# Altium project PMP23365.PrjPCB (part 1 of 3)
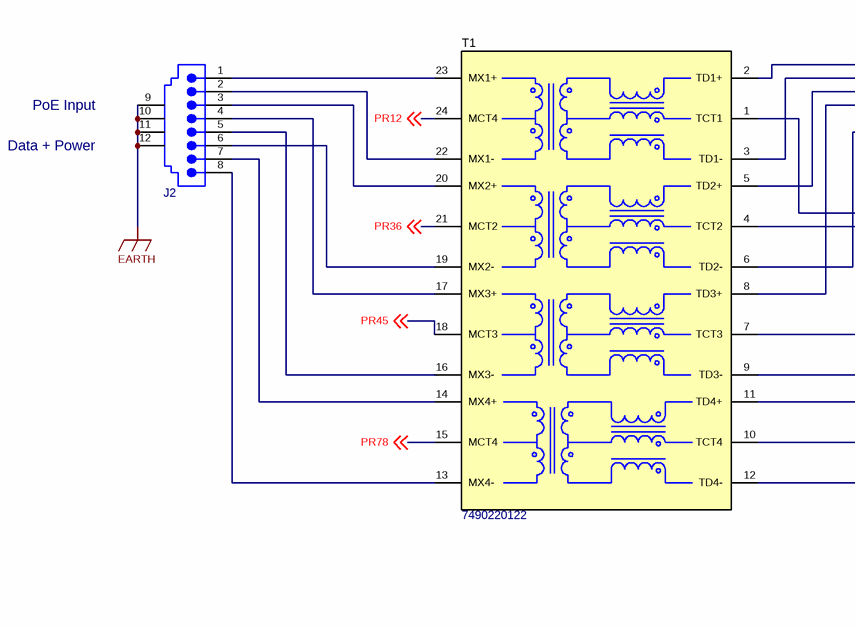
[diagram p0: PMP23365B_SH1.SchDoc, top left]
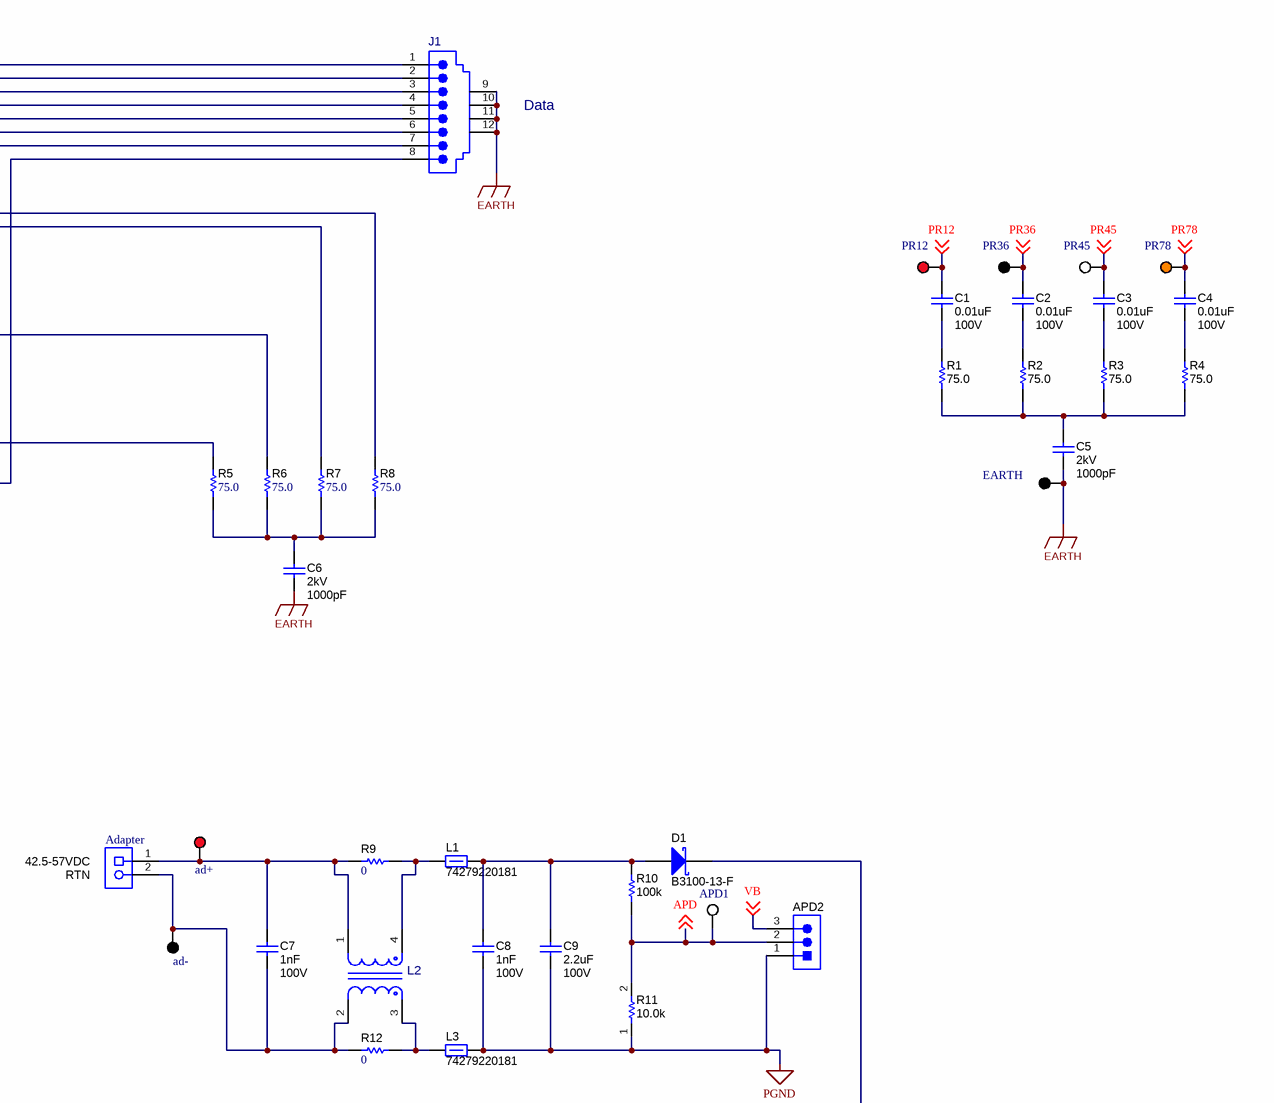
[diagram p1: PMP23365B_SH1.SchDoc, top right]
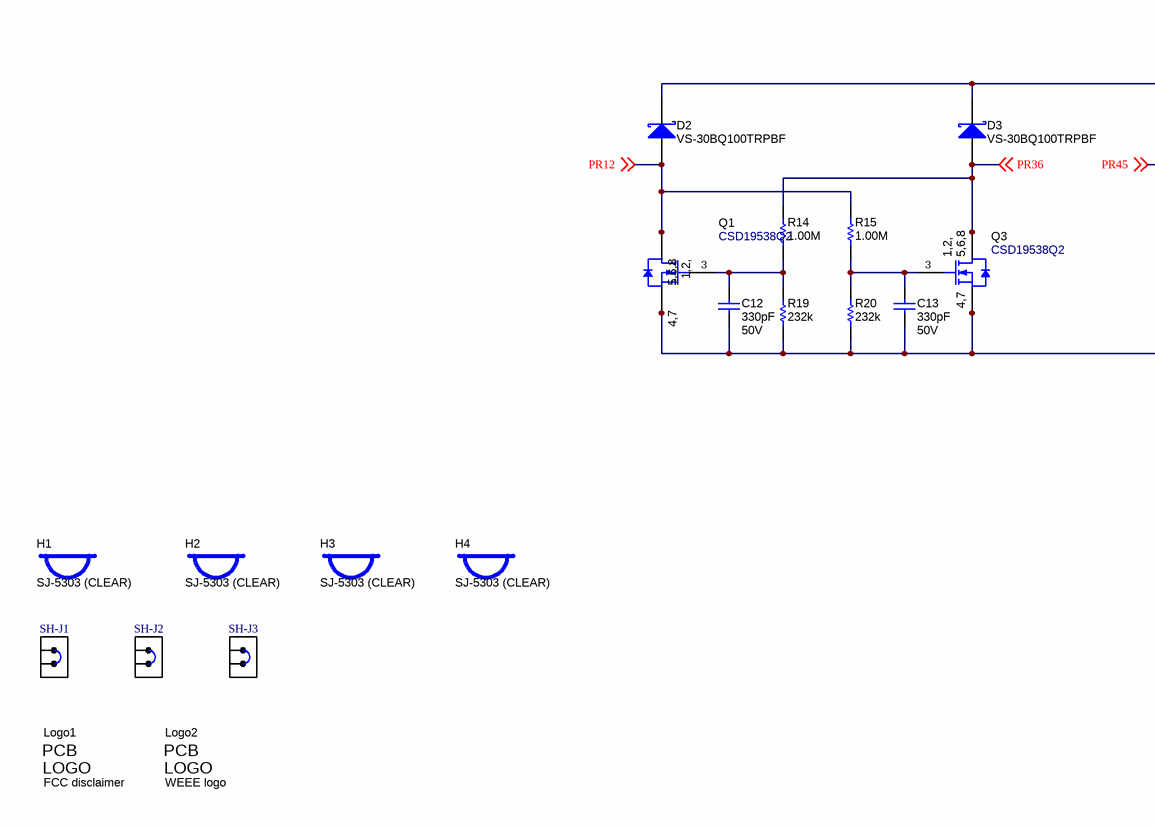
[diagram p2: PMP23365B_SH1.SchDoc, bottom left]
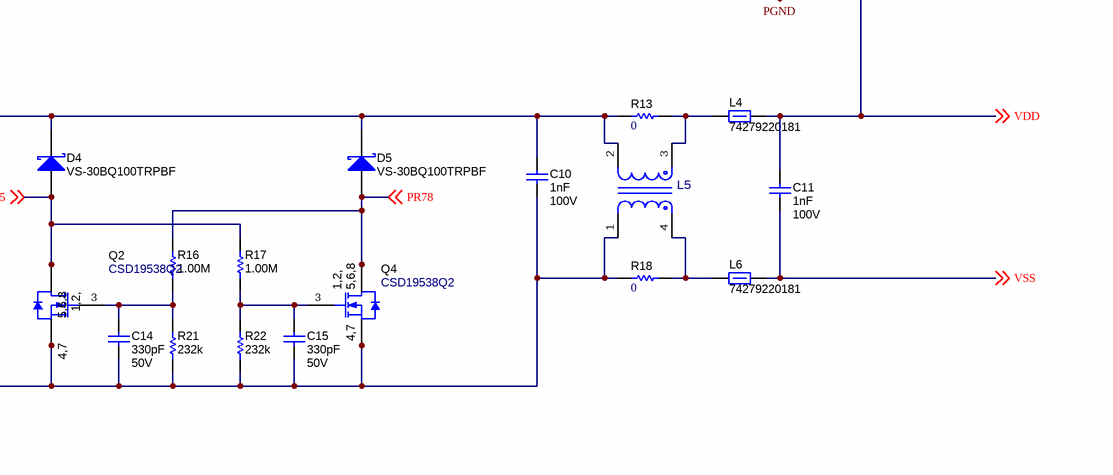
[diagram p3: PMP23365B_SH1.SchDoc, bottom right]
CopyrightYear: 2023; PCB_Layout: N/A; PCB_Rev: B; PRJ_Customer: Public Release; PRJ_Engineer: D Xing; PRJ_Number: PMP23365; PRJ_Title: TPS23730 with Telemetry at CLS8, 24V/3A; SCH_Rev: B; TechSupport: N/A; TID: N/A
3 sheets, 303 parts. Net scope: global (net labels, ports and power ports of the same name join across sheets).
Board file: PMP23365B.PcbDoc
Sheets:
  PMP23365B_SH1.SchDoc
  PMP23365B_SH2.SchDoc
  PMP23365B_SH3.SchDoc

## Sheet PMP23365B_SH1.SchDoc: PoE Input
size 558 x 431 mm; Date: Not shown in title block; ApprovedBy: Not shown in title block; CheckedBy: Not shown in title block; Author: Not shown in title block; CompanyName: Not shown in title block; DrawnBy: D Xing; Engineer: Not shown in title block; Organization: Not shown in title block; Address1: Not shown in title block; Address2: Not shown in title block; Address3: Not shown in title block; Address4: Not shown in title block; DocumentNumber: 1; Revision: Use project parameter SCH_Rev; SheetNumber: 1; SheetTotal: 3; PageSetup: Record=PageOptions¦CenterHorizontal=True¦CenterVertical=True¦PrintScale=1.00¦XCorrection=1.00¦YCorrection=1.00¦PrintKind=0¦BorderSize=5000000¦LeftOffset=0¦BottomOffset=0¦Orientation=2¦PaperLength=1000¦PaperWidth=1000¦Scale=100¦PaperSource=15¦PrintQuality=600¦MediaType=1¦DitherType=10¦PaperKind=Letter¦PrintScaleMode=1

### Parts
ad+  5000  [Keystone5000]  (value not drawn)
ad-  5001  [Keystone5001]  (value not drawn)
Adapter  CMP-0074913-1  [TERM_BLK_ED555-2DS]  (value not drawn)
APD1  5002  [Keystone5002]  (value not drawn)
APD2  5-146278-3  [TE_5-146278-3]  (value not drawn)
C1  ValueDisplayed: 0.01uF  Value2: 100V  [0603L]  (hidden comment: Capacitor)
C2  ValueDisplayed: 0.01uF  Value2: 100V  [0603L]  (hidden comment: Capacitor)
C3  ValueDisplayed: 0.01uF  Value2: 100V  [0603L]  (hidden comment: Capacitor)
C4  ValueDisplayed: 0.01uF  Value2: 100V  [0603L]  (hidden comment: Capacitor)
C5  VDC_V: 2kV  ValueDisplayed: 1000pF  [1812]  (hidden comment: GR443QR73D102KW01L)
C6  VDC_V: 2kV  ValueDisplayed: 1000pF  [1812]  (hidden comment: GR443QR73D102KW01L)
C7  Cap_F: 1nF  VDC_V: 100V  [0603]  (hidden comment: C1608X7R2A102K080AA)
C8  Cap_F: 1nF  VDC_V: 100V  [0603]  (hidden comment: C1608X7R2A102K080AA)
C9  ValueDisplayed: 2.2uF  Value2: 100V  [1210_270]  (hidden comment: Capacitor)
C10  Cap_F: 1nF  VDC_V: 100V  [0603]  (hidden comment: C1608X7R2A102K080AA)
C11  Cap_F: 1nF  VDC_V: 100V  [0603]  (hidden comment: C1608X7R2A102K080AA)
C12  ValueDisplayed: 330pF  VDC_V: 50V  [0603]  (hidden comment: GRM1885C1H331JA01D)
C13  ValueDisplayed: 330pF  VDC_V: 50V  [0603]  (hidden comment: GRM1885C1H331JA01D)
C14  ValueDisplayed: 330pF  VDC_V: 50V  [0603]  (hidden comment: GRM1885C1H331JA01D)
C15  ValueDisplayed: 330pF  VDC_V: 50V  [0603]  (hidden comment: GRM1885C1H331JA01D)
D1  B3100-13-F  [SMC]
D2  VS-30BQ100TRPBF  [SMC]
D3  VS-30BQ100TRPBF  [SMC]
D4  VS-30BQ100TRPBF  [SMC]
D5  VS-30BQ100TRPBF  [SMC]
EARTH  5001  [Keystone5001]  (value not drawn)
H1  SJ-5303 (CLEAR)  [Bumpon_SJ5003Transparent]
H2  SJ-5303 (CLEAR)  [Bumpon_SJ5003Transparent]
H3  SJ-5303 (CLEAR)  [Bumpon_SJ5003Transparent]
H4  SJ-5303 (CLEAR)  [Bumpon_SJ5003Transparent]
J1  1-406541-1  [TEC_1-406541-1]  (value not drawn)
J2  1-406541-1  [TEC_1-406541-1]  (value not drawn)
L1  74279220181  [0805_HV]
L2  CM7060P701R-10  [FP-CM7060P701R-10_SMT_CMC_7MM0_6MM0-MFG]  (value not drawn)
L3  74279220181  [0805_HV]
L4  74279220181  [0805_HV]
L5  CM7060P701R-10  [FP-CM7060P701R-10_SMT_CMC_7MM0_6MM0-MFG]  (value not drawn)
L6  74279220181  [0805_HV]
Logo1  FCC disclaimer  [FCC_disclaimer]  (no BOM)
Logo2  WEEE logo  [WEEE_Minimum]  (no BOM)
PR12  5000  [Keystone5000]  (value not drawn)
PR36  5001  [Keystone5001]  (value not drawn)
PR45  5002  [Keystone5002]  (value not drawn)
PR78  5003  [Keystone5003]  (value not drawn)
Q1  CSD19538Q2  [DQK0006C]
Q2  CSD19538Q2  [DQK0006C]
Q3  CSD19538Q2  [DQK0006C]
Q4  CSD19538Q2  [DQK0006C]
R1  ValueDisplayed: 75.0  [0603L]  (hidden comment: Resistor)
R2  ValueDisplayed: 75.0  [0603L]  (hidden comment: Resistor)
R3  ValueDisplayed: 75.0  [0603L]  (hidden comment: Resistor)
R4  ValueDisplayed: 75.0  [0603L]  (hidden comment: Resistor)
R5  ValueDisplayed: 75.0  [0603]  (hidden comment: RC0603FR-0775RL)
R6  ValueDisplayed: 75.0  [0603]  (hidden comment: RC0603FR-0775RL)
R7  ValueDisplayed: 75.0  [0603]  (hidden comment: RC0603FR-0775RL)
R8  ValueDisplayed: 75.0  [0603]  (hidden comment: RC0603FR-0775RL)
R9  ValueDisplayed: 0  [0805_HV]  (hidden comment: MCR10EZPJ000)
R10  ValueDisplayed: 100k  [0603]  (hidden comment: CRCW0603100KFKEA)
R11  ValueDisplayed: 10.0k  [0603]  (hidden comment: CRCW060310K0FKEA)
R12  ValueDisplayed: 0  [0805_HV]  (hidden comment: MCR10EZPJ000)
R13  ValueDisplayed: 0  [0805_HV]  (hidden comment: MCR10EZPJ000)
R14  ValueDisplayed: 1.00M  [0603]  (hidden comment: CMP-0022138-4)
R15  ValueDisplayed: 1.00M  [0603]  (hidden comment: CMP-0022138-4)
R16  ValueDisplayed: 1.00M  [0603]  (hidden comment: CMP-0022138-4)
R17  ValueDisplayed: 1.00M  [0603]  (hidden comment: CMP-0022138-4)
R18  ValueDisplayed: 0  [0805_HV]  (hidden comment: MCR10EZPJ000)
R19  ValueDisplayed: 232k  [0603]  (hidden comment: CMP-0022224-4)
R20  ValueDisplayed: 232k  [0603]  (hidden comment: CMP-0022224-4)
R21  ValueDisplayed: 232k  [0603]  (hidden comment: CMP-0022224-4)
R22  ValueDisplayed: 232k  [0603]  (hidden comment: CMP-0022224-4)
SH-J1  60900213421  [Wurth_60900213421]  (value not drawn)
SH-J2  60900213421  [Wurth_60900213421]  (value not drawn)
SH-J3  60900213421  [Wurth_60900213421]  (value not drawn)
T1  7490220122  [Wurth_7490220122]

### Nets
EARTH: C5.2 C6.2 EARTH.1 J1.9 J1.10 J1.11 J1.12 J2.9 J2.10 J2.11 J2.12
PGND: APD2.1 C8.2 C9.1 L3.2 R11.1
APD: APD1.1 APD2.2 R10.1 R11.2 ; off-sheet APD
PR12: C1.1 D2.2(A) PR12.1 Q1.1(D) Q1.2(D) Q1.5(D) Q1.6(D) Q1.8(D) R15.2 T1.24(MCT4) ; off-sheet PR12
PR36: C2.1 D3.2(A) PR36.1 Q3.1(D) Q3.2(D) Q3.5(D) Q3.6(D) Q3.8(D) R14.2 T1.21(MCT2) ; off-sheet PR36
PR45: C3.1 D4.2(A) PR45.1 Q2.1(D) Q2.2(D) Q2.5(D) Q2.6(D) Q2.8(D) R17.2 T1.18(MCT3) ; off-sheet PR45
PR78: C4.1 D5.2(A) PR78.1 Q4.1(D) Q4.2(D) Q4.5(D) Q4.6(D) Q4.8(D) R16.2 T1.15(MCT4) ; off-sheet PR78
VB: APD2.3 ; off-sheet VB
VDD: C11.1 D1.1(K) L4.2 ; off-sheet VDD
VSS: C11.2 L6.2 ; off-sheet VSS
Netad+_1: ad+.1 Adapter.1 C7.1 L2.1 R9.1
Netad-_1: ad-.1 Adapter.2 C7.2 L2.2 R12.1
NetC1_2: C1.2 R1.2
NetC2_2: C2.2 R2.2
NetC3_2: C3.2 R3.2
NetC4_2: C4.2 R4.2
NetC5_1: C5.1 R1.1 R2.1 R3.1 R4.1
NetC6_1: C6.1 R5.2 R6.2 R7.2 R8.2
NetC8_1: C8.1 C9.2 D1.2(A) L1.2 R10.2
NetC10_1: C10.1 D2.1(K) D3.1(K) D4.1(K) D5.1(K) L5.2 R13.1
NetC10_2: C10.2 C12.2 C13.2 C14.2 C15.2 L5.1 Q1.4(S) Q1.7(S) Q2.4(S) Q2.7(S) Q3.4(S) Q3.7(S) Q4.4(S) Q4.7(S) R18.1 R19.1 R20.1 R21.1 R22.1
NetC12_1: C12.1 Q1.3(G) R14.1 R19.2
NetC13_1: C13.1 Q3.3(G) R15.1 R20.2
NetC14_1: C14.1 Q2.3(G) R16.1 R21.2
NetC15_1: C15.1 Q4.3(G) R17.1 R22.2
NetJ1_1: J1.1 T1.2(TD1+)
NetJ1_2: J1.2 T1.3(TD1-)
NetJ1_3: J1.3 T1.5(TD2+)
NetJ1_4: J1.4 T1.8(TD3+)
NetJ1_5: J1.5 T1.9(TD3-)
NetJ1_6: J1.6 T1.6(TD2-)
NetJ1_7: J1.7 T1.11(TD4+)
NetJ1_8: J1.8 T1.12(TD4-)
NetJ2_1: J2.1 T1.23(MX1+)
NetJ2_2: J2.2 T1.22(MX1-)
NetJ2_3: J2.3 T1.20(MX2+)
NetJ2_4: J2.4 T1.17(MX3+)
NetJ2_5: J2.5 T1.16(MX3-)
NetJ2_6: J2.6 T1.19(MX2-)
NetJ2_7: J2.7 T1.14(MX4+)
NetJ2_8: J2.8 T1.13(MX4-)
NetL1_1: L1.1 L2.4 R9.2
NetL2_3: L2.3 L3.1 R12.2
NetL4_1: L4.1 L5.3 R13.2
NetL5_4: L5.4 L6.1 R18.2
NetR5_1: R5.1 T1.10(TCT4)
NetR6_1: R6.1 T1.7(TCT3)
NetR7_1: R7.1 T1.4(TCT2)
NetR8_1: R8.1 T1.1(TCT1)

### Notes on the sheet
- PoE Input
- Data
- Data + Power
- (near Adapter) 42.5-57VDC
- (near Adapter) RTN

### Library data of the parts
ad+ PR12 = CMP-0055137-1: Test Point, Miniature, Red, TH; Manufacturer: Keystone; CNHeader: FALSE; Green_Lifecycle: Active; Green_REACh: Passed; ContactFinish: Silver; CT: TRUE
ad- EARTH PR36 = CMP-0055138-1: Test Point, Miniature, Black, TH; Manufacturer: Keystone; CNHeader: FALSE; Green_Lifecycle: Active; Green_REACh: Passed; ContactFinish: Silver; CT: TRUE
Adapter = CMP-0074913-1: Terminal Block, 3.5mm Pitch, 2x1, TH; PartNumber: ED555/2DS; Manufacturer: On-Shore Technology; Cert_VDE: Y; CNHeader: False; Current_A: 6A; Green_Lifecycle: Active; Shrouded: N; Gender: Female; Green_REACh: Passed; Voltage_V: 150V; Row_Count: 1; Pitch_mm: 3.5; ContactFinish: Brass; CT: True
APD1 PR45 = CMP-0055139-1: Test Point, Miniature, White, TH; Manufacturer: Keystone; CNHeader: FALSE; Green_Lifecycle: Active; Green_REACh: Passed; ContactFinish: Silver; CT: TRUE
APD2 = CMP-0054951-1: Header, 100mil, 3x1, Tin, TH; Manufacturer: TE Connectivity; CNHeader: TRUE; Green_Lifecycle: Active; Green_REACh: Passed; CT: FALSE
C1-C4 = CMP-0007468-5: CAP, CERM, 0.01 uF, 100 V, +/- 10%, X7R, 0603; PartNumber: GRM188R72A103KA01D; Manufacturer: MuRata; Polarized: N; Value: 0.01uF; U/M: EA; Cap_F: 10nF; Value1: Unknown; TaMin_C: -55°C; TaMax_C: 125°C; Cap_Case: 0603; SizeArea_mm2: 1.28; SizeAreaWB_mm2: 4.68; SizeX_mm: 1.6; SizeY_mm: 0.8; SizeZ_mm: 1; AEC Category: Q200
C5 C6 = CMP-0009438-2: CAP, CERM, 1000 pF, 2000 V, +/- 10%, X7R, 1812; Manufacturer: MuRata; TaMin_C: -55°C; Polarized: N; SizeAreaWB_mm2: 23.1; Value1: Unknown; U/M: EA; Value: 1000pF; TaMax_C: 125°C; SizeZ_mm: 1.35; SizeX_mm: 4.5; SizeY_mm: 3.2; Value2: 2000V; SizeArea_mm2: 14.4; Cap_F: 1nF; AEC Category: Q200
C7 C8 C10 C11 = CMP-0007053-4: CAP, CERM, 1000 pF, 100 V, +/- 10%, X7R, 0603; Manufacturer: TDK; Polarized: N; Value: 1000pF; U/M: EA; Value1: Unknown; TaMin_C: -55°C; TaMax_C: 125°C; SizeAreaWB_mm2: 4.68; SizeZ_mm: 1; SizeX_mm: 1.6; SizeY_mm: 0.8; SizeArea_mm2: 1.28; AEC Category: Q200
C9 = CMP-0009232-2: CAP, CERM, 2.2 uF, 100 V, +/- 10%, X7R, 1210; PartNumber: GRM32ER72A225KA35L; Manufacturer: MuRata; Polarized: N; Value: 2.2uF; U/M: EA; Cap_F: 2.2µF; ESR_ohm: 7m; Value1: 0.007 ohm; IRMS_A: 4.4A; TaMin_C: -55°C; TaMax_C: 125°C; Cap_Case: 1210; SizeArea_mm2: 8; SizeAreaWB_mm2: 14.7; SizeX_mm: 3.2; SizeY_mm: 2.5; SizeZ_mm: 2.7; AEC Category: Q200
C12-C15 = CMP-0007209-4: CAP, CERM, 330 pF, 50 V, +/- 5%, C0G/NP0, 0603; Manufacturer: MuRata; Polarized: N; Value: 330pF; U/M: EA; Value1: Unknown; TaMin_C: -55°C; TaMax_C: 125°C; AEC Category: Q200; SizeAreaWB_mm2: 4.68; SizeZ_mm: 1; SizeX_mm: 1.6; SizeY_mm: 0.8; SizeArea_mm2: 1.28
D1 = CMP-0028411-1: Diode, Schottky, 100 V, 3 A, SMC; Manufacturer: Diodes Inc.; Io_A: 3A; Green_Lifecycle: Active; SizeAreaWB_mm2: 83.2686; Vr_V: 100V; Green_REACh: Passed; TJmax_C: 125°C; U/M: EA; Value: 100V; SizeZ_mm: 2.6; SizeX_mm: 8.13; SizeY_mm: 6.22; Vf_V: 790mV; Value2: 0.79V; SizeArea_mm2: 50.5686; AEC Category: Q101; RJC_CperW: 10
D2-D5 = CMP-0028623-2: Diode, Schottky, 100 V, 3 A, SMC; Manufacturer: Vishay-Semiconductor; SizeY_mm: 6.22; Green_REACh: Incomplete; TJmax_C: 175°C; AEC Category: Q101; Vf_V: 620mV; SizeX_mm: 8.13; Vr_V: 100V; Io_A: 3A; SizeAreaWB_mm2: 83.2686; SizeZ_mm: 2.6; Value: 100V; SizeArea_mm2: 50.5686; Green_Lifecycle: Not Set; RJC_CperW: 46; Value2: 0.62V
H1-H4 = CMP-0003620-1: Bumpon, Hemisphere, 0.44 X 0.20, Clear; Manufacturer: 3M
J1 J2 = CMP-0054918-1: RJ45, No LED, tab up, R/A, TH; Manufacturer: TE Connectivity; CNHeader: FALSE; Green_Lifecycle: Active; Green_REACh: Passed; ContactFinish: Gold; CT: TRUE
L1 L3 L4 L6 = CMP-0003134-1: Ferrite Bead, 180 ohm @ 100 MHz, 3.1 A, 0805; Manufacturer: Wurth Elektronik; Ztyp@1GHz_Ohm: 60.644; ZTyp@100MHz_Ohm: 180; SizeAreaWB_mm2: 6.75; DCR_ohm: 26.5m; Value1: 0.0265 ohm; Value: 180 ohm; Imax_A: 3.1A; SizeZ_mm: 1.45; SizeX_mm: 2; SizeY_mm: 1.25; SizeArea_mm2: 2.5
L2 L5 = CMP-0094039-1: Common Mode Choke Power 700Ω 4A -40 to 125°C Wire Wound Surface Mount T/R; Manufacturer: Laird; AEC Qualified: No; DCR_ohm: 15m; SizeZ_mm: 3.8mm; Impedance At Frequency: 700Ω @ 100MHz
Logo1 = CMP-0074847-1: FCC_disclaimer; Library Reference: Logo
Logo2 = CMP-0074769-1
PR78 = CMP-0055140-1: Test Point, Miniature, Orange, TH; Manufacturer: Keystone; CNHeader: FALSE; Green_Lifecycle: Active; Green_REACh: Passed; ContactFinish: Silver; CT: TRUE
Q1-Q4 = CMP-0000968-2: MOSFET, N-CH, 100 V, 4.5 A, DQK0006C (WSON-6); Alternate Manufacturer: None; Manufacturer: Texas Instruments; SizeZ_mm: 0.8; ChType: N; VdsMax_V: 100V; SizeX_mm: 2; SizeAreaWB_mm2: 9; Vgs_V: 20V; Value: 100V; SizeArea_mm2: 4; AEC Category: Q101; IdsMax_A: 4.5A; U/M: EA
R1-R4 = CMP-0022590-4: RES, 75.0, 1%, 0.1 W, AEC-Q200 Grade 0, 0603; PartNumber: CRCW060375R0FKEA; Manufacturer: Vishay-Dale; Value: 75.0; Res_ohm: 75; Value_Code: 75R0; Power_W: 100mW; Value2: 0.1W; VDC_V: 75V; TempCo: 100 ppm/C; SizeArea_mm2: 1.28; SizeX_mm: 1.6; SizeY_mm: 0.8; SizeZ_mm: 1; EIA_Code: E96; AEC Category: Q200; AEC Qualified: Y; AEC Grade: 0
R5-R8 = CMP-0023268-5: RES, 75.0, 1%, 0.1 W, 0603; Manufacturer: Yageo; Power_W: 100mW; TempCo: 100 ppm/C; Value_Code: 75R0; Value: 75.0; EIA_Code: E96; Res_ohm: 75; SizeX_mm: 1.6; SizeY_mm: 0.8; SizeZ_mm: 1; Value2: 0.1W; SizeArea_mm2: 1.28; AEC Qualified: N; VDC_V: 75V; AEC Category: Q200; SizeAreaWB_mm2: 4.68
R9 R12 R13 R18 = CMP-0020802-2: RES, 0, 5%, 0.125 W, 0805; Manufacturer: Rohm; Power_W: 125mW; TempCo: 400 ppm/C; Value_Code: 0000; U/M: EA; Value: 0; EIA_Code: E24; SizeX_mm: 2; SizeY_mm: 1.25; SizeZ_mm: 1.45; Value2: 0.125W; SizeArea_mm2: 2.5; VDC_V: 150V; AEC Category: Q200
R10 = CMP-0021990-4: RES, 100 k, 1%, 0.1 W, AEC-Q200 Grade 0, 0603; Manufacturer: Vishay-Dale; Power_W: 100mW; TempCo: 100 ppm/C; Value: 100k; EIA_Code: E96; SizeX_mm: 1.6; SizeY_mm: 0.8; SizeZ_mm: 1; Value2: 0.1W; SizeArea_mm2: 1.28; AEC Qualified: Y; VDC_V: 75V; AEC Category: Q200; AEC Grade: 0
R11 = CMP-0021998-4: RES, 10.0 k, 1%, 0.1 W, AEC-Q200 Grade 0, 0603; Manufacturer: Vishay-Dale; Power_W: 100mW; TempCo: 100 ppm/C; Value_Code: 10k0; Value: 10.0k; EIA_Code: E96; Res_ohm: 10k; SizeX_mm: 1.6; SizeY_mm: 0.8; SizeZ_mm: 1; Value2: 0.1W; SizeArea_mm2: 1.28; AEC Qualified: Y; VDC_V: 75V; AEC Category: Q200; AEC Grade: 0
R14-R17 = CMP-0022138-4: RES, 1.00 M, 1%, 0.1 W, AEC-Q200 Grade 0, 0603; PartNumber: CRCW06031M00FKEA; Manufacturer: Vishay-Dale; Value: 1.00Meg; Res_ohm: 1M; Value_Code: 1M00; Power_W: 100mW; Value2: 0.1W; VDC_V: 75V; TempCo: 100 ppm/C; EIA_Code: E96; AEC Category: Q200; AEC Qualified: Y; AEC Grade: 0; SizeX_mm: 1.6; SizeY_mm: 0.8; SizeZ_mm: 1; SizeArea_mm2: 1.28
R19-R22 = CMP-0022224-4: RES, 232 k, 1%, 0.1 W, AEC-Q200 Grade 0, 0603; PartNumber: CRCW0603232KFKEA; Manufacturer: Vishay-Dale; Value: 232k; Power_W: 100mW; Value2: 0.1W; VDC_V: 75V; TempCo: 100 ppm/C; EIA_Code: E96; AEC Category: Q200; AEC Qualified: Y; AEC Grade: 0; SizeX_mm: 1.6; SizeY_mm: 0.8; SizeZ_mm: 1; SizeArea_mm2: 1.28
SH-J1-SH-J3 = CMP-0003761-2: Shunt, 2.54mm, Gold, Black; Manufacturer: Wurth Elektronik
T1 = CMP-0030597-1: Transformer, 350 uH, SMT; Manufacturer: Wurth Elektronik; Value: 350uH; Ind_H: 350µH; Lp: 350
